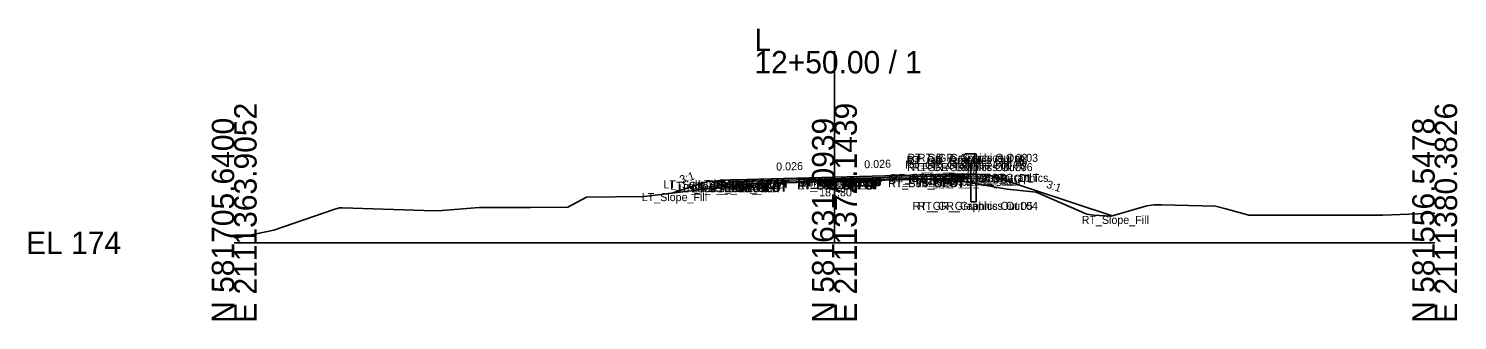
# Model space of a CAD drawing. Extents: x -486 to 1153, y -333 to 9539.
# Drawn here: x -25.7 to 152.8, y 1990.3 to 2026.7 of the extents above; entities that cross this region are included whole.
import ezdxf

# ---------------------------------------------------------------- set-up
doc = ezdxf.new("R2010")
doc.units = 0
for name, color, linetype in [('Default', 7, 'Continuous'), ('Exist Cross Section Cell', 7, 'Continuous'), ('Exist XS Ground Line', 7, 'Continuous'), ('Prop CMT Guardrail Graphics', 7, 'Continuous'), ('Prop CMT Pvmt Course 1', 7, 'Continuous'), ('Prop CMT Pvmt Course 2', 7, 'Continuous'), ('Prop CMT Pvmt Course 3', 7, 'Continuous'), ('Prop CMT Pvmt Surface', 7, 'Continuous'), ('Prop CMT Pvmt Surface Shoulder', 7, 'Continuous'), ('Prop CMT Shld Paved Course 1', 7, 'Continuous'), ('Prop CMT Shld Paved Course 2', 7, 'Continuous'), ('Prop CMT Shld Paved Course 3', 7, 'Continuous'), ('Prop CMT Slope Grass', 7, 'Continuous'), ('Prop CMT Subgrade Earthwork', 7, 'Continuous'), ('Prop XS Earthwork Shape', 7, 'Continuous'), ('Prop XS SE Text', 7, 'Continuous'), ('Prop XS Side Slope Text', 7, 'Continuous'), ('Scratch_Level_0', 7, 'Continuous')]:
    doc.layers.add(name, color=color, linetype=linetype)

msp = doc.modelspace()

# ---------------------------------------------------------------- linework, layer by layer
at = {"layer": 'Exist Cross Section Cell'}
for p, q in [((75, 2000), (75, 2023.95)), ((0, 2000), (75, 2000)), ((75, 2000), (150, 2000))]:
    msp.add_line(p, q, dxfattribs=at)
at = {"layer": 'Exist XS Ground Line'}
for p, q in [((51.24, 2005.77), (61.57, 2007.05)), ((61.57, 2007.05), (64.57, 2007.38)), ((64.57, 2007.38), (65.57, 2007.42)), ((65.57, 2007.42), (73.83, 2007.78)), ((73.83, 2007.78), (75, 2007.8)), ((75, 2007.8), (83.61, 2007.98)), ((83.61, 2007.98), (84.39, 2007.97)), ((84.39, 2007.97), (85.61, 2007.98)), ((85.61, 2007.98), (91.14, 2007.66)), ((91.14, 2007.66), (96.59, 2006.71)), ((96.59, 2006.71), (100.2, 2006.31)), ((41.67, 2004.43), (44.01, 2005.7)), ((44.01, 2005.7), (51.24, 2005.77)), ((100.2, 2006.31), (106.53, 2003.57)), ((4.96, 2001.56), (12.45, 2004.15)), ((12.45, 2004.15), (13.17, 2004.37)), ((13.17, 2004.37), (13.53, 2004.36)), ((13.53, 2004.36), (23.72, 2004.03)), ((23.72, 2004.03), (25.47, 2004.01)), ((25.47, 2004.01), (30.61, 2004.39)), ((30.61, 2004.39), (37.06, 2004.42)), ((37.06, 2004.42), (41.67, 2004.43)), ((106.53, 2003.57), (107.38, 2003.47)), ((107.38, 2003.47), (109.57, 2003.32)), ((109.57, 2003.32), (114.04, 2004.62)), ((114.04, 2004.62), (114.89, 2004.74)), ((114.89, 2004.74), (115.91, 2004.74)), ((115.91, 2004.74), (122.63, 2004.58)), ((122.63, 2004.58), (123.91, 2004.25)), ((123.91, 2004.25), (126.79, 2003.43)), ((126.79, 2003.43), (127.24, 2003.43)), ((127.24, 2003.43), (136.09, 2003.45)), ((136.09, 2003.45), (143.53, 2003.46)), ((143.53, 2003.46), (150, 2003.68)), ((0.53, 2000.67), (4.96, 2001.56)), ((0, 2000.65), (0.53, 2000.67))]:
    msp.add_line(p, q, dxfattribs=at)
at = {"layer": 'Prop CMT Guardrail Graphics'}
for points in [[(92.7, 2011.11), (91.37, 2011.11), (91.1, 2010.82)], [(91.1, 2010.82), (91.37, 2010.53)], [(91.37, 2010.53), (91.1, 2010.24)], [(92.7, 2005.11), (92.7, 2011.11)], [(91.1, 2010.24), (91.37, 2009.95), (92.04, 2009.95)], [(92.04, 2009.95), (92.04, 2005.11)], [(92.04, 2005.11), (92.7, 2005.11)]]:
    msp.add_lwpolyline(points, dxfattribs=at)
at = {"layer": 'Prop CMT Pvmt Course 1'}
for points in [[(75, 2008.2), (64, 2007.91)], [(64, 2007.71), (75, 2007.99)], [(64, 2007.91), (64, 2007.71)], [(75, 2008.2), (86, 2008.49)], [(86, 2008.28), (75, 2007.99)], [(75, 2007.99), (75, 2008.2)], [(75, 2007.99), (75, 2008.2)], [(86, 2008.49), (86, 2008.28)]]:
    msp.add_lwpolyline(points, dxfattribs=at)
msp.add_lwpolyline([(75, 2007.99), (75, 2008.08), (75, 2008.08), (75, 2007.99)], close=True, dxfattribs=at)
msp.add_lwpolyline([(75, 2007.99), (75, 2008.08), (75, 2008.08), (75, 2007.99)], close=True, dxfattribs=at)
at = {"layer": 'Prop CMT Pvmt Course 2'}
for points in [[(75, 2007.99), (64, 2007.71)], [(64, 2007.71), (64, 2007.37)], [(64, 2007.37), (75, 2007.66)], [(75, 2007.99), (86, 2008.28)], [(75, 2007.66), (75, 2007.99)], [(75, 2007.66), (75, 2007.99)], [(86, 2007.94), (75, 2007.66)], [(86, 2008.28), (86, 2007.94)]]:
    msp.add_lwpolyline(points, dxfattribs=at)
at = {"layer": 'Prop CMT Pvmt Course 3'}
for points in [[(75, 2007.66), (64, 2007.37)], [(64, 2007.37), (64, 2007.37)], [(75, 2007.66), (86, 2007.94)], [(75, 2007.66), (75, 2007.66)], [(75, 2007.66), (75, 2007.66)], [(86, 2007.94), (86, 2007.94)]]:
    msp.add_lwpolyline(points, dxfattribs=at)
at = {"layer": 'Prop CMT Pvmt Surface'}
for points in [[(75, 2008.2), (64, 2007.91)], [(75, 2008.2), (86, 2008.49)]]:
    msp.add_lwpolyline(points, dxfattribs=at)
at = {"layer": 'Prop CMT Pvmt Surface Shoulder'}
for points in [[(86, 2008.49), (91, 2008.62)], [(64, 2007.91), (62, 2007.86)]]:
    msp.add_lwpolyline(points, dxfattribs=at)
at = {"layer": 'Prop CMT Shld Paved Course 1'}
for points in [[(86, 2008.49), (91, 2008.62), (91.2, 2008.41)], [(64, 2007.91), (62, 2007.86), (61.79, 2007.65)], [(61.79, 2007.65), (64, 2007.71)], [(64, 2007.71), (64, 2007.91)], [(86, 2008.28), (86, 2008.49)], [(91.2, 2008.41), (86, 2008.28)]]:
    msp.add_lwpolyline(points, dxfattribs=at)
at = {"layer": 'Prop CMT Shld Paved Course 2'}
for points in [[(64, 2007.71), (61.79, 2007.65), (61.44, 2007.31)], [(61.44, 2007.31), (64, 2007.37)], [(64, 2007.37), (64, 2007.71)], [(86, 2008.28), (91.2, 2008.41), (91.53, 2008.09)], [(86, 2007.94), (86, 2008.28)], [(91.53, 2008.09), (86, 2007.94)]]:
    msp.add_lwpolyline(points, dxfattribs=at)
at = {"layer": 'Prop CMT Shld Paved Course 3'}
for points in [[(64, 2007.37), (61.44, 2007.31)], [(61.44, 2007.31), (61.44, 2007.31), (61.44, 2007.31)], [(64, 2007.37), (64, 2007.37)], [(86, 2007.94), (91.53, 2008.09)], [(86, 2007.94), (86, 2007.94)], [(91.53, 2008.09), (91.53, 2008.09), (91.53, 2008.09)]]:
    msp.add_lwpolyline(points, dxfattribs=at)
at = {"layer": 'Prop CMT Slope Grass'}
for points in [[(91, 2008.62), (91.1, 2008.61)], [(91.1, 2008.61), (94.1, 2008.51)], [(94.1, 2008.51), (109.71, 2003.36)], [(62, 2007.86), (59, 2007.62), (54.68, 2006.2)]]:
    msp.add_lwpolyline(points, dxfattribs=at)
at = {"layer": 'Prop CMT Subgrade Earthwork'}
for points in [[(91.53, 2008.09), (92.02, 2008.58)], [(61.44, 2007.31), (60.97, 2007.78)], [(64, 2007.37), (61.44, 2007.31)], [(75, 2007.66), (64, 2007.37)], [(75, 2007.66), (86, 2007.94)], [(86, 2007.94), (91.53, 2008.09)]]:
    msp.add_lwpolyline(points, dxfattribs=at)
at = {"layer": 'Prop XS Earthwork Shape'}
for points in [[(86.19, 2007.95), (91.14, 2007.66), (96.59, 2006.71), (100.2, 2006.31), (106.53, 2003.57), (107.38, 2003.47), (109.57, 2003.32), (109.71, 2003.36), (94.1, 2008.51), (92.02, 2008.58), (91.53, 2008.09)], [(65, 2007.4), (64, 2007.37), (61.44, 2007.31), (60.97, 2007.78), (59, 2007.62), (54.68, 2006.2), (61.57, 2007.05), (64.57, 2007.38)], [(65.57, 2007.42), (73.83, 2007.78), (75, 2007.8), (83.61, 2007.98), (84.39, 2007.97), (85.61, 2007.98), (86.19, 2007.95), (86, 2007.94), (75, 2007.66), (65, 2007.4)]]:
    msp.add_lwpolyline(points, close=True, dxfattribs=at)

# ---------------------------------------------------------------- texts
at = {"layer": 'Default'}
for s, height, p in [('181.80', 1, (73.09, 2005.8)), ('-', 0.0001, (0, 2000))]:
    msp.add_text(s, height=height, dxfattribs=at).set_placement(p)
at = {"layer": 'Exist Cross Section Cell'}
for s, p in [('L', (65, 2023.95)), ('12+50.00 / 1', (65, 2021.15)), ('EL 174', (-26, 1998.6))]:
    msp.add_text(s, height=2.8, dxfattribs=at).set_placement(p)
for s, p in [('E 2111363.9052', (2.8, 1990)), ('E 2111372.1439', (77.8, 1990)), ('E 2111380.3826', (152.8, 1990)), ('N 581705.6400', (0, 1990)), ('N 581631.0939', (75, 1990)), ('N 581556.5478', (150, 1990))]:
    msp.add_text(s, height=2.8, rotation=90, dxfattribs=at).set_placement(p)
at = {"layer": 'Prop XS SE Text'}
for p in [(78.73, 2009.3), (67.73, 2009.01)]:
    msp.add_text('0.026', height=1, rotation=1.4894, dxfattribs=at).set_placement(p)
at = {"layer": 'Prop XS Side Slope Text'}
for rotation, p in [(18.2629, (55.85, 2007.37)), (341.7371, (101.39, 2006.9))]:
    msp.add_text('3:1', height=1, rotation=rotation, dxfattribs=at).set_placement(p)
at = {"layer": 'Scratch_Level_0'}
for s, p in [('RT_GR_Graphics Out 08', (83.81, 2009.24)), ('RT_GR_Graphics Out 01', (83.99, 2009.82)), ('RT_GR_Graphics Out 09', (84.09, 2009.53)), ('RT_GR_Graphics Out 02', (84.11, 2010.11)), ('RT_GR_Graphics Out 03', (85.43, 2010.11)), ('RT_PV1_OEOT', (81.81, 2007.49)), ('RT_GS_OS_GR_Face_Graphics', (82.04, 2007.61)), ('RT_GR_Graphics Out 07', (84.07, 2008.95)), ('RT_Sub_Trench_Out_DLT', (84.61, 2007.58)), ('RT_GR_Graphics Out 06', (84.75, 2008.95)), ('RT_PS1_OEOP', (86.85, 2007.62)), ('RT_GS_OS_CTL', (89.5, 2007.51)), ('LT_Sub_Trench_Out_DLT', (53.62, 2006.78)), ('LT_GS_OS_CTL', (54.46, 2006.62)), ('LT_Sub_Trench_Out', (55.55, 2006.31)), ('LT_PS3_Shelf_Out', (56.1, 2006.31)), ('LT_PS3_OEOP', (57.23, 2006.31)), ('LT_PS2_OEOP', (57.57, 2006.65)), ('LT_PS1_OEOP', (57.91, 2006.86)), ('LT_PV2_OEOT', (59.75, 2006.71)), ('LT_PV3_OEOT', (59.75, 2006.37)), ('LT_Sub_OEOT', (59.77, 2006.37)), ('LT_PV1_OEOT', (59.87, 2006.91)), ('RT_PV2_OEEOP', (70.33, 2006.99)), ('RT_PV3_OEEOP', (70.33, 2006.66)), ('RT_Sub_OEEOP', (70.36, 2006.66)), ('LT_PV2_OEEOP', (70.39, 2006.99)), ('LT_PV3_OEEOP', (70.39, 2006.66)), ('LT_Sub_OEEOP', (70.42, 2006.66)), ('RT_PV1_OEEOP', (70.45, 2007.08)), ('LT_PV1_OEEOP', (70.51, 2007.08)), ('RT_PV2_IEEOP', (70.71, 2006.99)), ('LT_PV2_IEEOP', (70.77, 2006.99)), ('RT_PV1_IEEOP', (70.83, 2007.08)), ('LT_PV1_IEEOP', (70.89, 2007.08)), ('PV2_PGL', (72.35, 2006.99)), ('PV1_PGL', (72.47, 2007.2)), ('RT_PV2_OEOT', (81.69, 2007.28)), ('RT_PV3_OEOT', (81.69, 2006.94)), ('RT_Sub_OEOT', (81.71, 2006.94)), ('RT_Sub_Trench_Out', (85.58, 2007.09)), ('RT_PS3_Shelf_Out', (86.13, 2007.09)), ('RT_PS2_OEOP', (86.93, 2007.41)), ('RT_PS3_OEOP', (87.26, 2007.09)), ('LT_Slope_Fill', (50.92, 2005.2)), ('RT_GR_Graphics Out 05', (84.76, 2004.11)), ('RT_GR_Graphics Out 04', (85.41, 2004.11)), ('RT_Slope_Fill', (105.89, 2002.36))]:
    msp.add_text(s, height=1, dxfattribs=at).set_placement(p)

doc.saveas('drawing.dxf')
